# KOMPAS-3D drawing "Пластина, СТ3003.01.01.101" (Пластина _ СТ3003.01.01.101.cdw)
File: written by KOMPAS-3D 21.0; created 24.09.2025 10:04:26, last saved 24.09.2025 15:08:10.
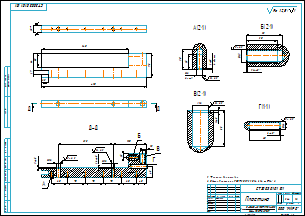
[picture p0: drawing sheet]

Sheet 1: A2, landscape

Document properties: Знак неуказанной шероховатости: 4; Параметр неуказанной шероховатости: Ra 12,5; Масса: 3.643787

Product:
- Part/product: Пластина  | designation СТ3003.01.01.101
    Материал: Лист$dБ-ПН-НО-25 ГОСТ 19903-2015;Ст3сп ГОСТ 14637-89$ (density 7850 kg/m3)
    Масса: 3.643787
    Форматы листов документа: A2

Title block, sheet 1: Наименование: Пластина; designation: СТ3003.01.01.101; Материал: Лист Б-ПН-НО-25 ГОСТ 19903-2015 Ст3сп ГОСТ 14637-89; Масса: 3,64; Количество листов документа: 1; organisation: ООО "МИРО"; Форматы листов документа: A2; stored path: C:\Users\1\Yandex.Disk\Документы\Новая папка\Стапель №2\Стапель _ СТ3003.00.00.000\Опора _ СТ3003.01.00.000\2D\Кронштейн _ СТ3003.01.01.000\Основание _ СТ3003.01.01.100\Пластина _ СТ3003.01.01.101.cdw; Разработал: Тимонин

Views: Вид 1, Снизу, Проекционный вид 3, Проекционный вид 5, Выносной элемент 6, Выносной элемент 7, Выносной элемент 8, Выносной элемент 9, Разрез Д-Д, Выносной элемент А, Выносной элемент, Выносной элемент Б, Выносной элемент В, Выносной элемент Г
Referenced files in C:\Users\1\Yandex.Disk\Документы\Новая папка\Стапель №2\Стапель _ СТ3003.00.00.000\Опора _ СТ3003.01.00.000\3D\Кронштейн _ СТ3003.01.01.000\Основание _ СТ3003.01.01.100\: Пластина _ СТ3003.01.01.101.m3d
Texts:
  Ra 6,3
  Ra 12,5
  Ra 12,5 ( )
  СТ3003.01.01.100
  СТ3003.01.01.101 Пластина
Dimensions and other numbers on the sheet: 410; 95; 340; 25; 55; 66; 17; 6; 6 отв.; 1; 6 фасок; 15; 20; 12; 1,6; 30; 35; 2; 16; 60; 1:2; 3,64

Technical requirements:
  *Размеры для справок.
  Общие допуски по ГОСТ 30893.1: Н14, h14, ± IT14/2.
